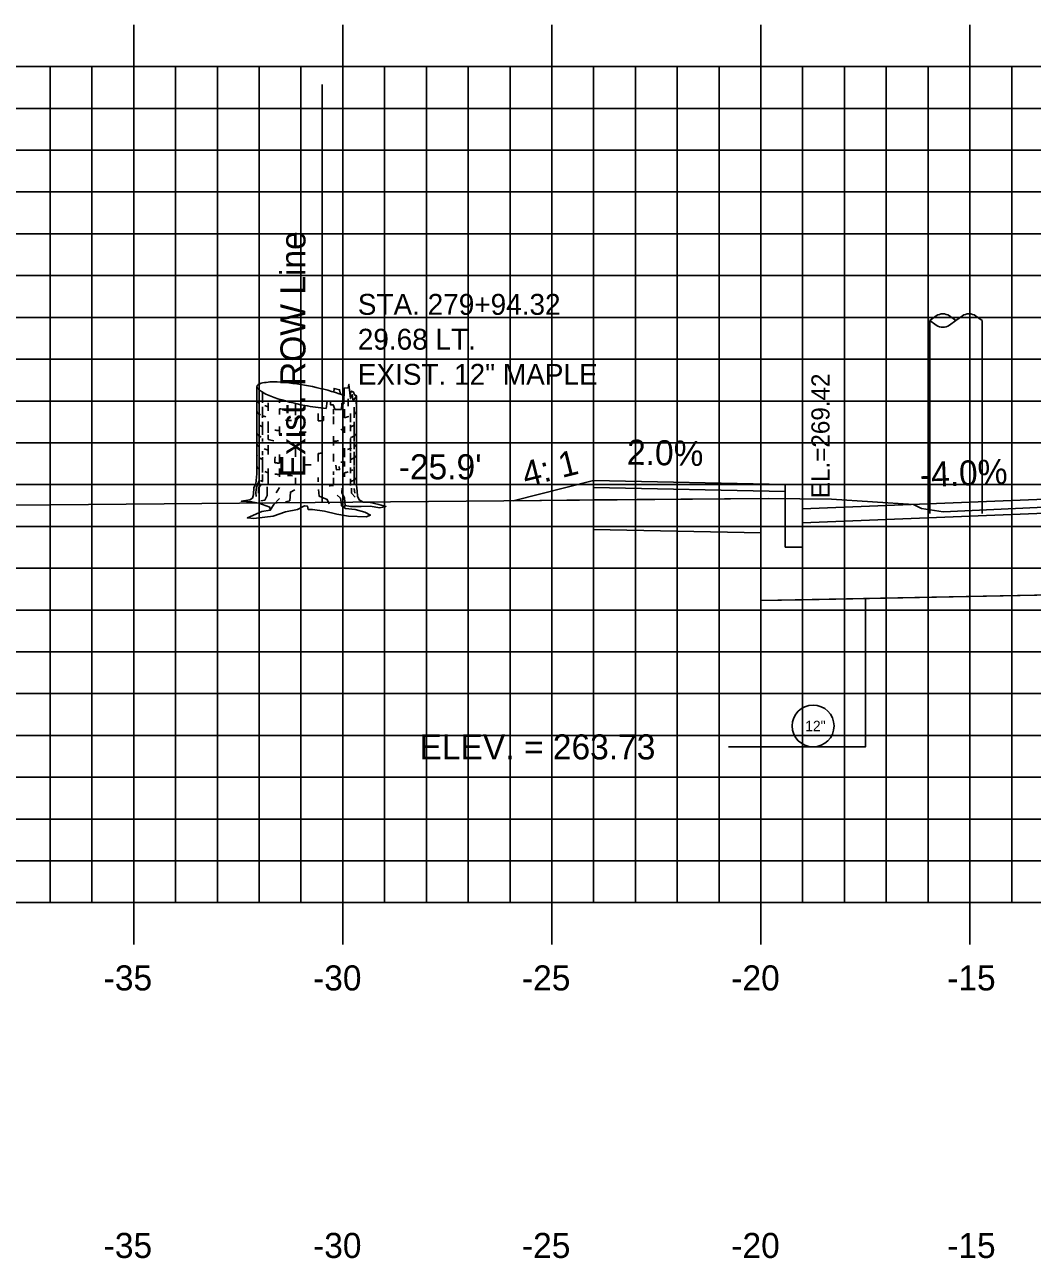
# Model space of a CAD drawing. Extents: x 855121 to 855291, y 366268 to 366378.
# Drawn here: x 855166.83 to 855190.94, y 366298.73 to 366328.24 of the extents above; entities that cross this region are included whole.
import ezdxf

# ---------------------------------------------------------------- set-up
doc = ezdxf.new("R2010")
doc.units = 0
for name, color, linetype in [('ANNOTATION', 7, 'Continuous'), ('D_Curb_Type_1_Lt', 7, 'Continuous'), ('D_Roadway_Edge_Shoulder', 7, 'Continuous'), ('D_Roadway_FinishedGrade', 7, 'Continuous'), ('D_Roadway_Sidewalks_Paved', 7, 'Continuous'), ('D_Roadway_SubGrade', 7, 'Continuous'), ('D_Text_Monospaced', 7, 'Continuous'), ('D_Text_Standard', 7, 'Continuous'), ('E_ROW_Line', 7, 'Continuous'), ('H_V ANNOTATION', 7, 'Continuous'), ('JUNK COM EXC', 7, 'Continuous'), ('JUNK FILL', 7, 'Continuous'), ('junk strct exc', 7, 'Continuous'), ('MAJOR', 7, 'Continuous'), ('MINOR', 7, 'Continuous'), ('PDRAIN', 7, 'Continuous'), ('S_Roadway_Centerline', 7, 'Continuous'), ('S_Trees_Decid_Pay', 7, 'Continuous'), ('S_Utilities_Pole_Power', 7, 'Continuous')]:
    doc.layers.add(name, color=color, linetype=linetype)

msp = doc.modelspace()

# ---------------------------------------------------------------- linework, layer by layer
at = {"layer": 'D_Curb_Type_1_Lt'}
msp.add_lwpolyline([(855185.025, 366317.24), (855185.025, 366315.74), (855185.442, 366315.74), (855185.442, 366317.24)], close=True, dxfattribs=at)
at = {"layer": 'D_Roadway_Edge_Shoulder'}
msp.add_lwpolyline([(855185.442, 366316.657), (855193.442, 366316.977), (855204.442, 366317.197), (855215.442, 366316.977), (855223.442, 366316.656)], dxfattribs=at)
at = {"layer": 'D_Roadway_FinishedGrade'}
msp.add_line((855178.52, 366316.852), (855180.437, 366317.332), dxfattribs=at)
at = {"layer": 'D_Roadway_Sidewalks_Paved'}
msp.add_lwpolyline([(855180.437, 366317.332), (855185.025, 366317.24), (855185.025, 366317.073), (855180.437, 366317.165)], close=True, dxfattribs=at)
at = {"layer": 'D_Roadway_SubGrade'}
msp.add_lwpolyline([(855180.437, 366317.165), (855180.437, 366316.165), (855184.442, 366316.085), (855184.442, 366314.463), (855185.442, 366314.483)], dxfattribs=at)
msp.add_lwpolyline([(855193.442, 366316.643), (855185.442, 366316.323), (855185.442, 366314.483), (855193.442, 366314.643)], close=True, dxfattribs=at)
at = {"layer": 'D_Text_Standard'}
msp.add_lwpolyline([(855184.442, 366310.962), (855184.352, 366310.962), (855183.672, 366310.962)], dxfattribs=at)
at = {"layer": 'E_ROW_Line'}
msp.add_line((855173.95, 366316.811), (855173.95, 366326.811), dxfattribs=at)
at = {"layer": 'JUNK COM EXC'}
for points in [[(855191.742, 366316.723), (855188.805, 366316.582), (855188.288, 366316.664), (855188.09, 366316.761), (855186.136, 366316.886), (855184.618, 366316.907), (855180.437, 366316.87)], [(855180.437, 366316.87), (855180.437, 366316.165), (855184.442, 366316.085), (855184.442, 366314.463), (855193.442, 366314.643)]]:
    msp.add_lwpolyline(points, dxfattribs=at)
at = {"layer": 'JUNK FILL'}
msp.add_lwpolyline([(855180.442, 366316.87), (855180.442, 366317.332), (855180.437, 366317.332), (855178.52, 366316.852)], close=True, dxfattribs=at)
at = {"layer": 'junk strct exc'}
msp.add_lwpolyline([(855184.442, 366314.463), (855184.442, 366310.962), (855186.942, 366310.962), (855186.942, 366314.513)], close=True, dxfattribs=at)
at = {"layer": 'MAJOR'}
for p, q in [((855169.442, 366328.238), (855169.442, 366327.236)), ((855174.442, 366328.238), (855174.442, 366327.236)), ((855179.442, 366328.238), (855179.442, 366327.236)), ((855184.442, 366328.238), (855184.442, 366327.236)), ((855189.442, 366328.238), (855189.442, 366327.236)), ((855134.442, 366327.236), (855274.442, 366327.236)), ((855134.442, 366327.236), (855274.442, 366327.236)), ((855169.442, 366307.236), (855169.442, 366327.236)), ((855174.442, 366307.236), (855174.442, 366327.236)), ((855179.442, 366307.236), (855179.442, 366327.236)), ((855184.442, 366307.236), (855184.442, 366327.236)), ((855189.442, 366307.236), (855189.442, 366327.236)), ((855134.442, 366322.236), (855274.442, 366322.236)), ((855134.442, 366317.236), (855274.442, 366317.236)), ((855134.442, 366312.236), (855274.442, 366312.236)), ((855134.442, 366307.236), (855274.442, 366307.236)), ((855134.442, 366307.236), (855274.442, 366307.236)), ((855169.442, 366306.234), (855169.442, 366307.236)), ((855174.442, 366306.234), (855174.442, 366307.236)), ((855179.442, 366306.234), (855179.442, 366307.236)), ((855184.442, 366306.234), (855184.442, 366307.236)), ((855189.442, 366306.234), (855189.442, 366307.236))]:
    msp.add_line(p, q, dxfattribs=at)
at = {"layer": 'MINOR'}
for p, q in [((855167.442, 366307.236), (855167.442, 366327.236)), ((855168.442, 366307.236), (855168.442, 366327.236)), ((855170.442, 366307.236), (855170.442, 366327.236)), ((855171.442, 366307.236), (855171.442, 366327.236)), ((855172.442, 366307.236), (855172.442, 366327.236)), ((855173.442, 366307.236), (855173.442, 366327.236)), ((855175.442, 366307.236), (855175.442, 366327.236)), ((855176.442, 366307.236), (855176.442, 366327.236)), ((855177.442, 366307.236), (855177.442, 366327.236)), ((855178.442, 366307.236), (855178.442, 366327.236)), ((855180.442, 366307.236), (855180.442, 366327.236)), ((855181.442, 366307.236), (855181.442, 366327.236)), ((855182.442, 366307.236), (855182.442, 366327.236)), ((855183.442, 366307.236), (855183.442, 366327.236)), ((855185.442, 366307.236), (855185.442, 366327.236)), ((855186.442, 366307.236), (855186.442, 366327.236)), ((855187.442, 366307.236), (855187.442, 366327.236)), ((855188.442, 366307.236), (855188.442, 366327.236)), ((855190.442, 366307.236), (855190.442, 366327.236)), ((855134.442, 366326.236), (855274.442, 366326.236)), ((855134.442, 366325.236), (855274.442, 366325.236)), ((855134.442, 366324.236), (855274.442, 366324.236)), ((855134.442, 366323.236), (855274.442, 366323.236)), ((855134.442, 366321.236), (855274.442, 366321.236)), ((855134.442, 366320.236), (855274.442, 366320.236)), ((855134.442, 366319.236), (855274.442, 366319.236)), ((855134.442, 366318.236), (855274.442, 366318.236)), ((855134.442, 366316.236), (855274.442, 366316.236)), ((855134.442, 366315.236), (855274.442, 366315.236)), ((855134.442, 366314.236), (855274.442, 366314.236)), ((855134.442, 366313.236), (855274.442, 366313.236)), ((855134.442, 366311.236), (855274.442, 366311.236)), ((855134.442, 366310.236), (855274.442, 366310.236)), ((855134.442, 366309.236), (855274.442, 366309.236)), ((855134.442, 366308.236), (855274.442, 366308.236))]:
    msp.add_line(p, q, dxfattribs=at)
at = {"layer": 'PDRAIN'}
msp.add_lwpolyline([(855184.442, 366314.463), (855184.442, 366310.962), (855186.942, 366310.962), (855186.942, 366314.463)], dxfattribs=at)
msp.add_circle((855185.692, 366311.462), 0.5, dxfattribs=at)
at = {"layer": 'S_Roadway_Centerline'}
msp.add_lwpolyline([(855146.902, 366317.671), (855147.024, 366317.289), (855147.254, 366316.598), (855147.777, 366316.658), (855148.726, 366316.597), (855149.663, 366316.602), (855156.3, 366316.664), (855158.414, 366316.671), (855184.618, 366316.907), (855186.136, 366316.886), (855188.09, 366316.761), (855188.288, 366316.664), (855188.805, 366316.582), (855191.742, 366316.723), (855194.375, 366316.881), (855201.614, 366317.202), (855204.941, 366317.345), (855209.434, 366317.327), (855215.662, 366317.297), (855220.47, 366317.191), (855224.022, 366317.119), (855228.553, 366317.499), (855228.791, 366317.564), (855239.683, 366317.672)], dxfattribs=at)
at = {"layer": 'S_Trees_Decid_Pay'}
for p, q in [((855172.442, 366319.49), (855172.442, 366319.369)), ((855172.522, 366319.445), (855172.522, 366319.192)), ((855172.442, 366319.317), (855172.442, 366319.103)), ((855172.522, 366319.096), (855172.522, 366318.832)), ((855172.655, 366319.192), (855172.655, 366319)), ((855172.927, 366319.279), (855172.927, 366319.192)), ((855173.31, 366319.178), (855173.31, 366318.897)), ((855174.567, 366319.287), (855174.567, 366319.112)), ((855174.716, 366319.086), (855174.716, 366318.832)), ((855172.442, 366319.058), (855172.442, 366318.72)), ((855172.927, 366319.051), (855172.927, 366318.912)), ((855173.31, 366318.832), (855173.31, 366318.729)), ((855173.856, 366318.941), (855173.856, 366318.761)), ((855173.983, 366318.768), (855173.977, 366318.875)), ((855174.221, 366319.04), (855174.221, 366318.92)), ((855174.221, 366318.869), (855174.221, 366318.684)), ((855174.482, 366319.038), (855174.482, 366318.833)), ((855174.63, 366318.941), (855174.63, 366318.729)), ((855172.442, 366318.603), (855172.442, 366318.243)), ((855172.522, 366318.735), (855172.522, 366318.426)), ((855172.655, 366318.749), (855172.655, 366318.472)), ((855172.927, 366318.626), (855172.927, 366318.434)), ((855174.482, 366318.626), (855174.482, 366318.472)), ((855174.63, 366318.663), (855174.63, 366318.515)), ((855174.716, 366318.735), (855174.716, 366318.266)), ((855172.442, 366318.206), (855172.442, 366317.757)), ((855172.522, 366318.338), (855172.522, 366318.271)), ((855172.655, 366318.426), (855172.655, 366318.317)), ((855172.655, 366318.183), (855172.655, 366317.955)), ((855174.221, 366318.397), (855174.221, 366318.169)), ((855174.63, 366318.338), (855174.63, 366318.037)), ((855174.716, 366318.214), (855174.716, 366318.081)), ((855172.522, 366318.037), (855172.522, 366317.94)), ((855172.522, 366317.889), (855172.522, 366317.529)), ((855172.927, 366317.955), (855172.927, 366317.747)), ((855173.31, 366318.117), (855173.31, 366317.897)), ((855173.856, 366317.983), (855173.856, 366317.786)), ((855174.221, 366317.971), (855174.221, 366317.786)), ((855174.482, 366318.109), (855174.482, 366317.889)), ((855174.63, 366318), (855174.63, 366317.757)), ((855174.716, 366318.023), (855174.716, 366317.697)), ((855172.442, 366317.691), (855172.442, 366317.409)), ((855172.655, 366317.625), (855172.655, 366317.242)), ((855172.927, 366317.625), (855172.927, 366317.426)), ((855174.482, 366317.789), (855174.482, 366317.668)), ((855174.63, 366317.646), (855174.63, 366317.506)), ((855174.716, 366317.668), (855174.716, 366317.249)), ((855172.522, 366317.477), (855172.522, 366317.31)), ((855173.31, 366317.397), (855173.31, 366317.224)), ((855173.856, 366317.403), (855173.856, 366317.3)), ((855174.221, 366317.551), (855174.221, 366317.474)), ((855174.221, 366317.397), (855174.221, 366317.224)), ((855174.482, 366317.518), (855174.482, 366317.419)), ((855174.63, 366317.374), (855174.63, 366317.218)), ((855172.931, 366317.168), (855172.851, 366317.037)), ((855174.713, 366317.145), (855174.727, 366317.028))]:
    msp.add_line(p, q, dxfattribs=at)
for points in [[(855174.767, 366319.361), (855174.767, 366317.224), (855174.787, 366317.082), (855174.793, 366316.956), (855174.836, 366316.869), (855174.929, 366316.82), (855175.065, 366316.82), (855175.308, 366316.764), (855175.475, 366316.715), (855175.332, 366316.684), (855175.095, 366316.722), (855174.885, 366316.709), (855174.624, 366316.715), (855174.5, 366316.733), (855174.47, 366316.691), (855174.408, 366316.733), (855174.507, 366316.666), (855174.742, 366316.641), (855174.972, 366316.579), (855175.102, 366316.509), (855175.003, 366316.466), (855174.581, 366316.485), (855174.303, 366316.528), (855174.004, 366316.604), (855173.718, 366316.641), (855173.613, 366316.641), (855173.595, 366316.722), (855173.527, 366316.728), (855173.36, 366316.641), (855173.074, 366316.585), (855172.775, 366316.478), (855172.316, 366316.429), (855172.162, 366316.441), (855172.504, 366316.592), (855172.707, 366316.623), (855172.695, 366316.697), (855172.435, 366316.796), (855172.26, 366316.827), (855172.019, 366316.838), (855172.218, 366316.876), (855172.279, 366316.913), (855172.303, 366316.999), (855172.316, 366317.168), (855172.361, 366317.254), (855172.389, 366317.495), (855172.389, 366319.581)], [(855174.388, 366319.399), (855174.367, 366319.507), (855174.235, 366319.538), (855174.228, 366319.45)], [(855174.41, 366319.033), (855174.418, 366319.178), (855174.464, 366319.17), (855174.478, 366319.544), (855174.572, 366319.552), (855174.587, 366319.632), (855174.624, 366319.295), (855174.67, 366319.39), (855174.69, 366319.235), (855174.767, 366319.361), (855174.761, 366319.171)], [(855174.767, 366319.361), (855174.721, 366319.384), (855174.698, 366319.449), (855174.647, 366319.472), (855174.613, 366319.397)], [(855174.249, 366319.038), (855174.212, 366319.141), (855174.147, 366319.147), (855174.147, 366319.229), (855174.072, 366319.235), (855174.048, 366319.055)], [(855172.813, 366317.76), (855172.815, 366317.837), (855172.822, 366317.903)], [(855174.359, 366317.668), (855174.367, 366317.594), (855174.293, 366317.588), (855174.279, 366317.705)], [(855172.44, 366317.337), (855172.38, 366317.176), (855172.366, 366317.051), (855172.374, 366316.954)], [(855172.497, 366317.256), (855172.426, 366317.153), (855172.426, 366317.028)], [(855172.637, 366317.182), (855172.637, 366316.977), (855172.58, 366316.867), (855172.483, 366316.851)], [(855173.292, 366317.108), (855173.189, 366317.057), (855173.175, 366316.851), (855173.072, 366316.822)], [(855173.858, 366317.117), (855173.875, 366316.962), (855174.072, 366316.882), (855174.118, 366316.779)], [(855174.5, 366316.733), (855174.482, 366316.913), (855174.42, 366317.049), (855174.427, 366317.149)], [(855174.647, 366317.153), (855174.653, 366317.028), (855174.735, 366316.934)], [(855172.707, 366316.623), (855172.794, 366316.764), (855172.926, 366316.907)], [(855174.309, 366316.981), (855174.384, 366316.913), (855174.402, 366316.814), (855174.408, 366316.733)]]:
    msp.add_lwpolyline(points, dxfattribs=at)
for centre, radius, start, end in [((855172.621, 366319.199), 0.48, 101.7221, 110.0157), ((855172.788, 366318.396), 1.299, 86.3056, 101.7221), ((855172.477, 366313.58), 6.126, 79.2221, 86.3056), ((855172.436, 366319.581), 0.0467, 169.2221, 180.9043), ((855172.444, 366319.581), 0.0544, 180.9043, 191.7221), ((855172.436, 366319.581), 0.0467, 157.54, 169.2221), ((855172.454, 366319.584), 0.0645, 191.7221, 204.3989), ((855172.443, 366319.578), 0.0544, 146.7221, 157.54), ((855172.493, 366319.601), 0.107, 204.3989, 214.2221), ((855172.452, 366319.573), 0.0645, 134.0453, 146.7221), ((855172.539, 366319.633), 0.164, 214.2221, 228.4286), ((855172.481, 366319.542), 0.107, 124.2221, 134.0453), ((855172.513, 366319.495), 0.164, 110.0157, 124.2221), ((855172.749, 366319.869), 0.48, 228.4286, 236.7221), ((855173.199, 366320.555), 1.299, 236.7221, 252.1387), ((855172.477, 366313.58), 6.126, 72.1387, 79.2221), ((855173.957, 366318.173), 1.299, 66.6931, 72.1387), ((855172.444, 366319.255), 0.0554, 191.6815, 202.5), ((855172.453, 366319.259), 0.0657, 202.5, 215.1737), ((855172.488, 366319.284), 0.109, 215.1737, 225), ((855172.529, 366319.324), 0.166, 225, 238.33), ((855173.001, 366320.344), 1.292, 250.9084, 254.4349), ((855174.679, 366325.148), 6.126, 252.1387, 259.2221), ((855174.679, 366325.148), 6.126, 259.2221, 264.0853), ((855172.445, 366318.994), 0.0554, 191.6815, 202.5), ((855172.454, 366318.998), 0.0657, 202.5, 215.1737), ((855172.489, 366319.023), 0.109, 215.1737, 225), ((855172.53, 366319.063), 0.166, 225, 239.1924), ((855172.693, 366319.336), 0.484, 239.1924, 242.5838), ((855173.002, 366320.083), 1.292, 247.5, 251.9171), ((855173.577, 366324.931), 5.916, 263.6913, 265.0485), ((855173.578, 366324.671), 5.916, 265.1076, 266.4618), ((855173.578, 366324.671), 5.916, 272.6957, 273.9224), ((855174.679, 366325.148), 6.126, 265.9754, 266.3056), ((855174.368, 366320.332), 1.299, 266.3056, 271.8711), ((855174.154, 366320.083), 1.292, 284.7144, 289.3881), ((855174.626, 366319.063), 0.166, 300.8076, 315), ((855174.666, 366319.023), 0.109, 315, 324.8263), ((855174.702, 366318.998), 0.0657, 324.8263, 337.5), ((855174.711, 366318.994), 0.0554, 337.5, 348.3185), ((855174.719, 366318.992), 0.0476, 348.3185, 0), ((855172.53, 366318.8), 0.166, 238.3999, 239.1924), ((855172.693, 366319.073), 0.484, 239.1924, 247.5), ((855173.002, 366319.819), 1.292, 247.5, 248.1929), ((855173.002, 366319.819), 1.292, 261.6338, 262.8454), ((855173.578, 366324.407), 5.916, 262.8454, 263.6816), ((855173.578, 366324.407), 5.916, 268.2292, 269.8838), ((855174.154, 366319.819), 1.292, 280.7368, 284.7144), ((855174.154, 366319.819), 1.292, 291.6463, 292.5), ((855174.463, 366319.073), 0.484, 292.5, 300.8076), ((855174.626, 366318.8), 0.166, 300.8076, 302.9622), ((855174.719, 366318.471), 0.0476, 348.3185, 0), ((855172.445, 366318.473), 0.0554, 191.6815, 202.5), ((855172.445, 366318.216), 0.0554, 191.6815, 202.5), ((855172.454, 366318.477), 0.0657, 202.5, 215.1737), ((855172.454, 366318.22), 0.0657, 202.5, 215.1737), ((855172.489, 366318.502), 0.109, 215.1737, 225), ((855172.489, 366318.245), 0.109, 215.1737, 225), ((855172.53, 366318.543), 0.166, 225, 239.1924), ((855172.693, 366318.815), 0.484, 239.1924, 245.3628), ((855173.002, 366319.562), 1.292, 254.3895, 260.7435), ((855173.578, 366324.15), 5.916, 276.2405, 277.1546), ((855174.154, 366319.562), 1.292, 277.1546, 278.1274), ((855174.154, 366319.562), 1.292, 291.5158, 292.5), ((855174.463, 366318.815), 0.484, 294.2275, 300.8076), ((855174.626, 366318.543), 0.166, 300.8076, 315), ((855174.666, 366318.502), 0.109, 315, 324.8263), ((855174.666, 366318.245), 0.109, 315, 324.8263), ((855174.702, 366318.477), 0.0657, 324.8263, 337.5), ((855174.702, 366318.22), 0.0657, 324.8263, 337.5), ((855174.711, 366318.473), 0.0554, 337.5, 348.3185), ((855174.711, 366318.216), 0.0554, 337.5, 348.3185), ((855174.719, 366318.214), 0.0476, 348.3185, 0), ((855172.445, 366317.95), 0.0554, 191.6815, 202.5), ((855172.53, 366318.285), 0.166, 225, 237.9306), ((855173.002, 366319.304), 1.292, 249.8999, 254.3895), ((855173.578, 366323.892), 5.916, 272.6957, 273.7279), ((855174.154, 366319.304), 1.292, 288.201, 292.5), ((855174.626, 366318.285), 0.166, 300.8076, 315), ((855174.626, 366318.02), 0.166, 300.8076, 315), ((855174.666, 366317.979), 0.109, 315, 324.8263), ((855174.702, 366317.954), 0.0657, 324.8263, 337.5), ((855174.711, 366317.95), 0.0554, 337.5, 348.3185), ((855174.719, 366317.948), 0.0476, 348.3185, 0), ((855172.445, 366317.678), 0.0554, 191.6815, 202.5), ((855172.454, 366317.682), 0.0657, 202.5, 215.1737), ((855172.489, 366317.707), 0.109, 215.1737, 225), ((855172.53, 366317.748), 0.166, 225, 237.9306), ((855172.53, 366318.02), 0.166, 237.9306, 239.1924), ((855172.693, 366318.292), 0.484, 239.1924, 247.5), ((855173.002, 366319.039), 1.292, 261.6205, 262.8454), ((855173.578, 366323.627), 5.916, 262.8454, 263.6816), ((855173.578, 366323.627), 5.916, 269.7243, 270), ((855173.578, 366323.627), 5.916, 270, 271.0793), ((855174.154, 366319.039), 1.292, 280.7537, 284.7144), ((855174.154, 366319.039), 1.292, 291.6463, 292.5), ((855174.463, 366318.292), 0.484, 292.5, 300.8076), ((855174.463, 366318.021), 0.484, 292.5, 297.266), ((855172.693, 366317.763), 0.484, 243.4501, 247.5), ((855172.993, 366318.513), 1.292, 247.9396, 248.6304), ((855173.002, 366318.767), 1.292, 250.8466, 254.3895), ((855173.002, 366318.767), 1.292, 261.6338, 262.8454), ((855173.578, 366323.355), 5.916, 262.8454, 263.6816), ((855173.578, 366323.355), 5.916, 265.539, 266.7363), ((855174.154, 366318.767), 1.292, 284.7144, 288.6336), ((855174.154, 366318.51), 1.292, 291.6463, 292.5), ((855174.463, 366317.763), 0.484, 292.5, 300.8076), ((855174.626, 366317.49), 0.166, 300.8076, 315), ((855174.666, 366317.45), 0.109, 315, 324.8263), ((855174.702, 366317.425), 0.0657, 324.8263, 337.5), ((855174.711, 366317.421), 0.0554, 337.5, 348.3185), ((855174.719, 366317.419), 0.0476, 348.3185, 0), ((855173.578, 366323.098), 5.916, 275.2344, 276.2169)]:
    msp.add_arc(centre, radius, start, end, dxfattribs=at)
at = {"layer": 'S_Utilities_Pole_Power'}
for p, q in [((855188.483, 366321.162), (855188.639, 366321.272)), ((855188.483, 366316.542), (855188.486, 366321.162)), ((855188.639, 366321.051), (855188.483, 366321.162)), ((855188.952, 366321.272), (855189.108, 366321.162)), ((855189.108, 366321.162), (855188.952, 366321.051)), ((855189.265, 366321.272), (855189.108, 366321.162)), ((855189.733, 366321.162), (855189.577, 366321.272)), ((855189.733, 366316.542), (855189.736, 366321.162))]:
    msp.add_line(p, q, dxfattribs=at)
for centre, start, end in [((855188.796, 366321.051), 90, 125.2644), ((855188.796, 366321.051), 54.7356, 90), ((855189.421, 366321.051), 90, 125.2644), ((855189.421, 366321.051), 54.7356, 90), ((855188.796, 366321.272), 234.7356, 270), ((855188.796, 366321.272), 270, 305.2644)]:
    msp.add_arc(centre, 0.271, start, end, dxfattribs=at)

# ---------------------------------------------------------------- texts
at = {"layer": 'ANNOTATION'}
for s, rotation, p in [('2.0%', 358.8542, (855181.235, 366317.716)), ('4: 1', 14.0362, (855178.82, 366317.177)), ('-4.0%', 2.2906, (855188.258, 366317.17))]:
    msp.add_text(s, height=0.6, rotation=rotation, dxfattribs=at).set_placement(p)
at = {"layer": 'D_Text_Monospaced'}
for s, height, p in [('STA. 279+94.32', 0.49998, (855174.801, 366321.298)), ('29.68 LT.', 0.5, (855174.801, 366320.464)), ('EXIST. 12" MAPLE', 0.49998, (855174.801, 366319.624))]:
    msp.add_text(s, height=height, dxfattribs=at).set_placement(p)
at = {"layer": 'D_Text_Standard'}
msp.add_text(' EL.=269.42', height=0.4335, rotation=90, dxfattribs=at).set_placement((855186.085, 366316.751))
for s, p in [("-25.9'", (855175.78, 366317.363)), ('ELEV. = 263.73', (855176.277, 366310.662))]:
    msp.add_text(s, height=0.6, dxfattribs=at).set_placement(p)
at = {"layer": 'E_ROW_Line'}
msp.add_text('Exist. ROW Line', height=0.6, rotation=90, dxfattribs=at).set_placement((855173.55, 366317.411))
at = {"layer": 'H_V ANNOTATION'}
for s, p in [('-35', (855168.722, 366305.136)), ('-30', (855173.73, 366305.136)), ('-25', (855178.727, 366305.136)), ('-20', (855183.735, 366305.136)), ('-15', (855188.899, 366305.136)), ('-35', (855168.722, 366298.736)), ('-30', (855173.73, 366298.736)), ('-25', (855178.727, 366298.736)), ('-20', (855183.735, 366298.736)), ('-15', (855188.899, 366298.736))]:
    msp.add_text(s, height=0.6, dxfattribs=at).set_placement(p)
at = {"layer": 'PDRAIN'}
msp.add_text('12"', height=0.25, dxfattribs=at).set_placement((855185.501, 366311.337))

doc.saveas('drawing.dxf')
